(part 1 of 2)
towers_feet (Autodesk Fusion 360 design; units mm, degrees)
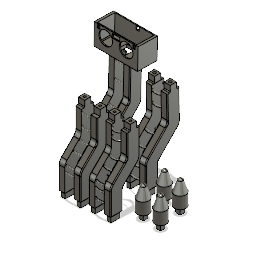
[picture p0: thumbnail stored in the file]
sketch "Sketch1" plane through (0, 0, 0) normal (0, 1, 0) x axis (1, 0, 0)
  line L1 (31.4678, 7.6066) -> (-53.5322, 7.6066)
  line L2 (-53.5322, -77.3934) -> (31.4678, -77.3934)
  line L3 (-53.5322, 7.6066) -> (-53.5322, -77.3934)
  line L4 (-24.0269, 7.6066) -> (-16.0269, 7.6066)
  line L5 (-24.0269, 23.3155) -> (-24.0269, 7.6066)
  line L6 (-16.0269, 7.6066) -> (-16.0269, 23.3155)
  line L7 (3.9731, 7.6066) -> (-4.0269, 7.6066)
  line L8 (3.9731, 23.3155) -> (3.9731, 7.6066)
  line L9 (-4.0269, 7.6066) -> (-4.0269, 23.3155)
  line L10 (-69.5322, -10.1974) -> (-53.5322, -10.1974)
  line L11 (-53.5322, -18.1974) -> (-69.5322, -18.1974)
  line L12 (-53.5322, -10.1974) -> (-53.5322, -18.1974)
  line L13 (-69.5322, -30.1974) -> (-53.5322, -30.1974)
  line L14 (-53.5322, -38.1974) -> (-69.5322, -38.1974)
  line L15 (-53.5322, -30.1974) -> (-53.5322, -38.1974)
  line L16 (-24.0269, -93.3934) -> (-24.0269, -77.3934)
  line L17 (-16.0269, -93.3934) -> (-16.0269, -77.3934)
  line L18 (-4.0269, -93.3934) -> (-4.0269, -77.3934)
  line L19 (3.9731, -93.3934) -> (3.9731, -77.3934)
  line L20 (31.4678, -77.3934) -> (31.4678, 7.6066)
  line L21 (47.4678, -18.1974) -> (31.4678, -18.1974)
  line L22 (47.4678, -10.1974) -> (31.4678, -10.1974)
  line L23 (47.4678, -30.1974) -> (31.4678, -30.1974)
  line L24 (47.4678, -38.1974) -> (31.4678, -38.1974)
  line L25 (-59.6337, -72.3934) -> (-62.6337, -72.3934)
  line L26 (37.4678, -72.3934) -> (40.4678, -72.3934)
  line L27 (-59.6337, 2.6066) -> (-62.6337, 2.6066)
  line L28 (37.4678, 2.6066) -> (40.4678, 2.6066)
  line L29 (-59.6337, -72.3934) -> (-59.6337, 2.6066)
  line L30 (37.4678, 2.6066) -> (37.4678, -72.3934)
  line L31 (-62.6337, -72.3934) -> (-62.6337, 2.6066)
  line L32 (40.4678, -72.3934) -> (40.4678, 2.6066)
  line L33 (-69.5322, -18.1974) -> (-69.5322, -10.1974)
  line L34 (-69.5322, -38.1974) -> (-69.5322, -30.1974)
  line L35 (47.4678, -18.1974) -> (47.4678, -10.1974)
  line L36 (47.4678, -38.1974) -> (47.4678, -30.1974)
  line L37 (-16.0269, -93.3934) -> (-24.0269, -93.3934)
  line L38 (3.9731, -93.3934) -> (-4.0269, -93.3934)
  line L39 (-4.0269, 23.3155) -> (3.9731, 23.3155)
  line L40 (-24.0269, 23.3155) -> (-16.0269, 23.3155)
  line L41 (-5, -80) -> (-15, -80)
  line L42 (-5, -85) -> (-5, -80)
  line L43 (-15, -85) -> (-5, -85)
  line L44 (-15, -80) -> (-15, -85)
  line L45 (-5, 10) -> (-15, 10)
  line L46 (-5, 15) -> (-5, 10)
  line L47 (-15, 15) -> (-5, 15)
  line L48 (-15, 10) -> (-15, 15)
  line L49 (-64, -19) -> (-69, -19)
  line L50 (-64, -29) -> (-64, -19)
  line L51 (-69, -29) -> (-64, -29)
  line L52 (-69, -19) -> (-69, -29)
  line L53 (46.4751, -19) -> (41.4751, -19)
  line L54 (46.4751, -29) -> (46.4751, -19)
  line L55 (41.4751, -29) -> (46.4751, -29)
  line L56 (41.4751, -19) -> (41.4751, -29)
  line L57 (63.9678, 9.8155) -> (63.9678, 30.1039)
  line L58 (-86.0322, -99.8934) -> (-86.0322, -79.8934)
  line L59 (63.9678, -79.8934) -> (63.9678, -99.8934)
  line L60 (53.9678, -109.8934) -> (33.9678, -109.8934)
  line L61 (-76.0322, -109.8934) -> (-56.0322, -109.8934)
  line L62 (-86.0322, 10.1066) -> (-86.0322, 30.1026)
  line L63 (53.9691, 40.1039) -> (33.9678, 40.1066)
  line L64 (-76.0322, 40.1026) -> (-56.0322, 40.1026)
  curve K1 (-62.3587, -78.4407) -> (-62.3587, -78.4407)
  line L65 (-68.03, -97.893) -> (-74.03, -97.893)
  line L66 (-68.03, -91.893) -> (-68.03, -97.893)
  line L67 (-74.03, -91.893) -> (-68.03, -91.893)
  line L68 (-74.03, -97.893) -> (-74.03, -91.893)
  line L69 (51.9678, -97.8934) -> (45.9678, -97.8934)
  line L70 (51.9678, -91.8934) -> (51.9678, -97.8934)
  line L71 (45.9678, -91.8934) -> (51.9678, -91.8934)
  line L72 (45.9678, -97.8934) -> (45.9678, -91.8934)
  line L73 (51.9678, 22.1046) -> (45.9678, 22.1046)
  line L74 (51.9678, 28.1046) -> (51.9678, 22.1046)
  line L75 (45.9678, 28.1046) -> (51.9678, 28.1046)
  line L76 (45.9678, 22.1046) -> (45.9678, 28.1046)
  line L77 (-68, 22) -> (-74, 22)
  line L78 (-68, 28) -> (-68, 22)
  line L79 (-74, 28) -> (-68, 28)
  line L80 (-74, 22) -> (-74, 28)
  line L81 (33.4678, -36.6974) -> (44.9678, -36.6974)
  line L82 (33.4678, -31.6974) -> (33.4678, -36.6974)
  line L83 (44.9678, -31.6974) -> (33.4678, -31.6974)
  line L84 (44.9678, -36.6974) -> (44.9678, -31.6974)
  line L85 (33.4678, -16.6974) -> (44.9678, -16.6974)
  line L86 (33.4678, -11.6974) -> (33.4678, -16.6974)
  line L87 (44.9678, -11.6974) -> (33.4678, -11.6974)
  line L88 (44.9678, -16.6974) -> (44.9678, -11.6974)
  line L89 (-2.5269, 20.8155) -> (2.4731, 20.8155)
  line L90 (-2.5269, 9.3155) -> (-2.5269, 20.8155)
  line L91 (2.4731, 9.3155) -> (-2.5269, 9.3155)
  line L92 (2.4731, 20.8155) -> (2.4731, 9.3155)
  line L93 (-22.5269, 20.8155) -> (-17.5269, 20.8155)
  line L94 (-22.5269, 9.3155) -> (-22.5269, 20.8155)
  line L95 (-17.5269, 9.3155) -> (-22.5269, 9.3155)
  line L96 (-17.5269, 20.8155) -> (-17.5269, 9.3155)
  line L97 (-55.5322, -11.6974) -> (-67.0322, -11.6974)
  line L98 (-55.5322, -16.6974) -> (-55.5322, -11.6974)
  line L99 (-67.0322, -16.6974) -> (-55.5322, -16.6974)
  line L100 (-67.0322, -11.6974) -> (-67.0322, -16.6974)
  line L101 (-55.5322, -31.6974) -> (-67.0322, -31.6974)
  line L102 (-55.5322, -36.6974) -> (-55.5322, -31.6974)
  line L103 (-67.0322, -36.6974) -> (-55.5322, -36.6974)
  line L104 (-67.0322, -31.6974) -> (-67.0322, -36.6974)
  line L105 (-17.5269, -90.8934) -> (-22.5269, -90.8934)
  line L106 (-17.5269, -79.3934) -> (-17.5269, -90.8934)
  line L107 (-22.5269, -79.3934) -> (-17.5269, -79.3934)
  line L108 (-22.5269, -90.8934) -> (-22.5269, -79.3934)
  line L109 (2.4731, -90.8934) -> (-2.5269, -90.8934)
  line L110 (2.4731, -79.3934) -> (2.4731, -90.8934)
  line L111 (-2.5269, -79.3934) -> (2.4731, -79.3934)
  line L112 (-2.5269, -90.8934) -> (-2.5269, -79.3934)
  circle C1 centre (48.9678, 25.1046) radius 7.5
  circle C2 centre (-71.0322, 25.1066) radius 7.5
  circle C3 centre (-71.0322, -94.8934) radius 7.5
  circle C4 centre (48.9678, -94.8934) radius 7.5
  arc A1 centre (-11.0349, 100.0947) radius 74.9921 clockwise from (33.9678, 40.1066) to (-56.0322, 40.1026)
  arc A2 centre (123.5319, -35.039) radius 74.5641 clockwise from (63.9678, -79.8934) to (63.9678, 9.8155)
  arc A3 centre (-11.0322, -169.8934) radius 75 clockwise from (-56.0322, -109.8934) to (33.9678, -109.8934)
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  point P4 (-53.5322, -77.3934)
  point P5 (-53.5322, 7.6066)
  point P28 (-62.6337, -72.3934)
  point P29 (-59.6337, -72.3934)
  point P30 (40.4678, -72.3934)
  point P31 (37.4678, -72.3934)
  point P32 (-62.6337, 2.6066)
  point P33 (-59.6337, 2.6066)
  point P34 (40.4678, 2.6066)
  point P35 (37.4678, 2.6066)
  point P52 (-15, -80)
  point P53 (-5, -80)
  point P55 (-15, -85)
  point P56 (-15, 10)
  point P57 (-5, 10)
  point P59 (-15, 15)
  point P60 (-69, -19)
  point P63 (-69, -29)
  point P64 (41.4751, -19)
  point P65 (46.4751, -19)
  point P67 (41.4751, -29)
  point P96 (-74.03, -97.893)
  point P99 (-74.03, -91.893)
  point P97 (-68.03, -97.893)
  point P19 (48.9678, -94.8934)
  point P112 (44.9678, -36.6974)
  point P113 (33.4678, -36.6974)
  point P115 (44.9678, -31.6974)
  point P116 (44.9678, -16.6974)
  point P117 (33.4678, -16.6974)
  point P119 (44.9678, -11.6974)
  point P120 (2.4731, 20.8155)
  point P121 (-2.5269, 20.8155)
  point P123 (2.4731, 9.3155)
  point P124 (-17.5269, 20.8155)
  point P125 (-22.5269, 20.8155)
  point P127 (-17.5269, 9.3155)
  point P128 (-67.0322, -11.6974)
  point P129 (-55.5322, -11.6974)
  point P131 (-67.0322, -16.6974)
  point P132 (-67.0322, -31.6974)
  point P133 (-55.5322, -31.6974)
  point P135 (-67.0322, -36.6974)
  point P136 (-22.5269, -90.8934)
  point P139 (-22.5269, -79.3934)
  point P137 (-17.5269, -90.8934)
  point P140 (-2.5269, -90.8934)
  point P141 (2.4731, -90.8934)
  point P143 (-2.5269, -79.3934)
  dimension "d124" diameter C2 = 15
  dimension "d162" distance P4 P5 = 85
  dimension "d167" distance L6 L9 = 12
  dimension "d169" distance L11 L13 = 12
  dimension "d179" distance P28 P29 = 3
  dimension "d181" distance P30 P31 = 3
  dimension "d183" distance P32 P33 = 3
  dimension "d186" distance P34 P35 = 3
  dimension "d188" distance L2 L25 = 5
  dimension "d189" distance L2 L26 = 5
  dimension "d192" distance L1 L28 = 5
  dimension "d193" distance L1 L27 = 5
  dimension "d407" distance P52 P53 = 10
  dimension "d408" distance P52 P55 = 5
  dimension "d409" distance P56 P57 = 10
  dimension "d410" distance P56 P59 = 5
  dimension "d412" distance P60 P63 = 10
  dimension "d413" distance P64 P65 = 5
  dimension "d414" distance P64 P67 = 10
  dimension "d502" radius = 10
  dimension "d588" distance P96 P99 = 6
  dimension "d589" distance P96 P97 = 6
  dimension "d597" distance P19 L72 = 3
  dimension "d655" distance P112 P113 = 11.5
  dimension "d656" distance P112 P115 = 5
  dimension "d657" distance L36 L84 = 2.5
  dimension "d658" distance L23 L83 = 1.5
  dimension "d659" distance P116 P117 = 11.5
  dimension "d660" distance P116 P119 = 5
  dimension "d661" distance L21 L85 = 1.5
  dimension "d662" distance L35 L88 = 2.5
  dimension "d663" distance P120 P121 = 5
  dimension "d664" distance P120 P123 = 11.5
  dimension "d665" distance L8 L92 = 1.5
  dimension "d666" distance L39 L89 = 2.5
  dimension "d671" distance P124 P125 = 5
  dimension "d672" distance P124 P127 = 11.5
  dimension "d673" distance L40 L93 = 2.5
  dimension "d674" distance L5 L94 = 1.5
  dimension "d675" distance L6 L96 = 1.5
  dimension "d676" distance P128 P129 = 11.5
  dimension "d677" distance P128 P131 = 5
  dimension "d678" distance L33 L100 = 2.5
  dimension "d679" distance L11 L99 = 1.5
  dimension "d680" distance P132 P133 = 11.5
  dimension "d681" distance P132 P135 = 5
  dimension "d682" distance L34 L104 = 2.5
  dimension "d683" distance L14 L103 = 1.5
  dimension "d684" distance P136 P139 = 11.5
  dimension "d685" distance P136 P137 = 5
  dimension "d686" distance L37 L105 = 2.5
  dimension "d687" distance L17 L106 = 1.5
  dimension "d688" distance P140 P141 = 5
  dimension "d689" distance P140 P143 = 11.5
  dimension "d690" distance L38 L109 = 2.5
  dimension "d691" distance L19 L110 = 1.5
  dimension "d692" distance L106 L112 = 15
  dimension "d693" distance L99 L101 = 15
  dimension "d694" distance L90 L96 = 15
  dimension "d695" distance L83 L85 = 15
extrude "Extrude9" new body sketch "Sketch1" profile of C1 C2 C3 C4 against normal blind 15
sketch "Sketch3" plane through (0, 0, 0) normal (1, 0, 0) x axis (0, 0, -1)
  line L1 (-77.6845, 0) -> (-89.6845, 0)
  line L2 (-81.7624, 30.5676) -> (-81.7624, 0.5676)
  line L3 (-109.6726, 59.221) -> (-81.7624, 30.5676)
  line L4 (-109.0151, 94.2149) -> (-109.6726, 59.221)
  line L5 (23.3155, 0) -> (7.6066, 0)
  line L6 (10, 30.5) -> (10, 0.5)
  line L7 (37.7935, 59.2667) -> (10, 30.5)
  line L8 (38.6405, 99.2577) -> (37.7935, 59.2667)
  point P4 (-81.7624, 0.5676)
  point P5 (-81.7624, 30.5676)
  point P6 (-109.6726, 59.221)
  point P7 (-109.0151, 94.2149)
  point P10 (10, 0.5)
  point P11 (10, 30.5)
  point P12 (37.7935, 59.2667)
  point P13 (38.6405, 99.2577)
  dimension "d21" distance P4 P5 = 30
  dimension "d23" distance P5 P6 = 40
  dimension "d24" distance P6 P7 = 35
  dimension "d26" distance P10 P11 = 30
  dimension "d28" distance P11 P12 = 40
  dimension "d29" distance P12 P13 = 40
sweep "Sweep2" sketch "Sketch1" TwistAngle 0 TaperAngle 0
sweep "Sweep1" sketch "Sketch1" TwistAngle 0 TaperAngle 0
sketch "Sketch4"
  line L1 (31.4678, 0) -> (43.352, 0)
  line L2 (34, 31) -> (34, 1)
  line L3 (55.2132, 52.2132) -> (34, 31)
  line L4 (55.2132, 82.2132) -> (55.2132, 52.2132)
  line L5 (-56.9466, 31) -> (-56.9466, 1)
  line L6 (-78.1598, 52.2132) -> (-56.9466, 31)
  line L7 (-78.1598, 82.2132) -> (-78.1598, 52.2132)
  point P4 (34, 1)
  point P5 (34, 31)
  point P6 (55.2132, 52.2132)
  point P7 (55.2132, 82.2132)
  point P10 (-78.1598, 52.2132)
  point P11 (-78.1598, 82.2132)
  dimension "d42" distance P4 P5 = 30
  dimension "d44" distance P5 P6 = 30
  dimension "d45" distance P6 P7 = 30
  dimension "d415" distance P10 P11 = 30
sweep "Sweep3" sketch "Sketch1" TwistAngle 0 TaperAngle 0
sweep "Sweep4" sketch "Sketch1" TwistAngle 0 TaperAngle 0
fillet "Fillet1" radius 1
work_plane "WorkPlane1" AlongDistance 15
sketch "Sketch8" plane through (-71.0322, -30, -24.8155) normal (0, -1, 0) x axis (1, 0, 0)
  circle C1 centre (0, 0) radius 2.5
  dimension "d136" diameter C1 = 5
loft "Loft1" sketch "Sketch8"
work_plane "WorkPlane2" AlongDistance 15
sketch "Sketch9" plane through (-71.0322, -30, 95.1845) normal (0, -1, 0) x axis (1, 0, 0)
  circle C1 centre (0, 0) radius 2.5
  dimension "d138" diameter C1 = 5
loft "Loft2" sketch "Sketch9"
work_plane "WorkPlane3" AlongDistance 15
sketch "Sketch10" plane through (48.9678, -30, -24.8155) normal (0, -1, 0) x axis (1, 0, 0)
  circle C1 centre (0, 0) radius 2.5
  dimension "d140" diameter C1 = 5
loft "Loft3" sketch "Sketch10"
work_plane "WorkPlane4" AlongDistance 15
sketch "Sketch11" plane through (48.9678, -30, 95.1845) normal (0, -1, 0) x axis (1, 0, 0)
  circle C1 centre (0, 0) radius 2.5
  dimension "d142" diameter C1 = 5
loft "Loft4" sketch "Sketch11"
fillet "Fillet5" radius 3
sketch "Sketch12" plane through (0, 0, 18.1974) normal (0, 0, 1) x axis (1, 0, 0)
  line L1 (-53.5322, 0) -> (-69.5322, 0)
  line L2 (-90.7454, 82.2132) -> (-74.7454, 82.2132)
  line L3 (-53.5322, 32.4143) -> (-53.5322, 0)
  line L4 (-74.7454, 53.6275) -> (-53.5322, 32.4143)
  line L5 (-74.7454, 82.2132) -> (-74.7454, 53.6275)
  line L6 (-90.7454, 47.0001) -> (-90.7454, 82.2132)
  line L7 (-69.5322, 25.7869) -> (-90.7454, 47.0001)
  line L8 (-69.5322, 0) -> (-69.5322, 25.7869)
sketch "Sketch13" plane through (0, 0, 0) normal (0, 1, 0) x axis (1, 0, 0)
sketch "Sketch18" plane through (0, 0, 18.1974) normal (0, 0, 1) x axis (1, 0, 0)
  line L1 (-90.7454, 47.0001) -> (-90.7454, 82.2132)
  line L2 (68.681, 47.0001) -> (68.681, 92.2132)
  circle C1 centre (-89.7454, 79) radius 1
  circle C2 centre (-75.7454, 79) radius 1
  circle C3 centre (-89.7454, 63.5) radius 1
  circle C4 centre (-75.7454, 63.5) radius 1
  circle C5 centre (-87.8667, 48.3965) radius 1
  circle C6 centre (-73.032, 49.7524) radius 1
  circle C7 centre (-65.5074, 41.1094) radius 1
  circle C8 centre (-56.2089, 29.9048) radius 1
  circle C9 centre (-54.7124, 23.0048) radius 1
  circle C10 centre (-54.765, 11.5923) radius 1
  circle C11 centre (-68.3402, 11.4595) radius 1
  circle C12 centre (-68, 23) radius 1
  circle C13 centre (-70, 29) radius 1
  circle C14 centre (-81, 40) radius 1
  circle C15 centre (-89.7454, 79) radius 1
  circle C16 centre (-75.7454, 79) radius 1
  circle C17 centre (-89.7454, 63.5) radius 1
  circle C18 centre (-75.7454, 63.5) radius 1
  circle C19 centre (-81, 40) radius 1
  circle C20 centre (-87.8667, 48.3965) radius 1
  circle C21 centre (-70, 29) radius 1
  circle C22 centre (-68, 23) radius 1
  circle C23 centre (-54.7124, 23.0048) radius 1
  circle C24 centre (-56.2089, 29.9048) radius 1
  circle C25 centre (-65.5074, 41.1094) radius 1
  circle C26 centre (-68.3402, 11.4595) radius 1
  circle C27 centre (-54.765, 11.5923) radius 1
  circle C28 centre (67.681, 69.5) radius 1
  circle C29 centre (53.681, 79) radius 1
  circle C30 centre (53.681, 69.5) radius 1
  circle C31 centre (53.681, 69.5) radius 1
  circle C32 centre (67.681, 69.5) radius 1
  circle C33 centre (67.681, 79) radius 1
  circle C34 centre (46.2758, 11.4595) radius 1
  circle C35 centre (46.2758, 11.4595) radius 1
  circle C36 centre (32.7006, 11.5923) radius 1
  circle C37 centre (32.7006, 11.5923) radius 1
  circle C38 centre (34.1444, 29.9048) radius 1
  circle C39 centre (43.4429, 41.1094) radius 1
  circle C40 centre (43.4429, 41.1094) radius 1
  circle C41 centre (47.9356, 29) radius 1
  circle C42 centre (58.9356, 40) radius 1
  circle C43 centre (47.9356, 29) radius 1
  circle C44 centre (65.8022, 48.3965) radius 1
  circle C45 centre (45.9356, 23) radius 1
  circle C46 centre (65.8022, 48.3965) radius 1
  circle C47 centre (32.648, 23.0048) radius 1
  circle C48 centre (50.9676, 49.7524) radius 1
  circle C49 centre (32.648, 23.0048) radius 1
  circle C50 centre (34.1444, 29.9048) radius 1
  circle C51 centre (67.681, 79) radius 1
  circle C52 centre (45.9356, 23) radius 1
  circle C53 centre (58.9356, 40) radius 1
  point P4 (-89.7454, 79)
  dimension "d269" diameter C1 = 2
  dimension "d270" distance L1 P4 = 1
  dimension "d275" diameter C7 = 2
  dimension "d276" diameter C8 = 2
  dimension "d277" diameter C9 = 2
  dimension "d278" diameter C10 = 2
  dimension "d279" diameter C14 = 2
  dimension "d280" diameter C13 = 2
  dimension "d281" diameter C12 = 2
  dimension "d282" diameter C11 = 2
  dimension "d305" diameter C15 = 2
  dimension "d306" diameter C25 = 2
  dimension "d307" diameter C24 = 2
  dimension "d308" diameter C23 = 2
  dimension "d309" diameter C27 = 2
  dimension "d310" diameter C19 = 2
  dimension "d311" diameter C21 = 2
  dimension "d312" diameter C22 = 2
  dimension "d313" diameter C26 = 2
sketch "Sketch21" plane through (0, 82.2132, 0) normal (0, 1, 0) x axis (-1, 0, 0)
  line L1 (89.7454, 10.1974) -> (75.7454, 10.1974)
  line L2 (90.7454, 18.1974) -> (90.7454, 11.1974)
  line L3 (74.7454, 18.1974) -> (90.7454, 18.1974)
  line L4 (74.7454, 11.1974) -> (74.7454, 18.1974)
  arc A1 centre (75.7454, 11.1974) radius 1 clockwise from (75.7454, 10.1974) to (74.7454, 11.1974)
  arc A2 centre (89.7454, 11.1974) radius 1 clockwise from (90.7454, 11.1974) to (89.7454, 10.1974)
  arc A3 centre (81.1475, 25.0943) radius 11.819 clockwise from (90.2904, 32.584) to (90.7454, 18.1974)
  arc A4 centre (86.0713, 24.3961) radius 12.9112 clockwise from (74.7454, 18.1974) to (75.5878, 31.9324)
  arc A5 centre (-57.1895, 24.4354) radius 7.6575 clockwise from (-56, 32) to (-52.7483, 18.1974)
  arc A6 centre (-64.8318, 24.7359) radius 7.5808 clockwise from (-68.6681, 18.1974) to (-67, 32)
  arc A7 centre (-54.9641, 24.3467) radius 14.8392 clockwise from (-43.4429, 33.699) to (-43.4429, 14.9945)
sweep "Sweep15" sketch "Sketch18" TwistAngle 0 TaperAngle 0
sweep "Sweep14" sketch "Sketch18" TwistAngle 0 TaperAngle 0
sweep "Sweep13" sketch "Sketch18" TwistAngle 0 TaperAngle 0
sweep "Sweep12" sketch "Sketch18" TwistAngle 0 TaperAngle 0
sweep "Sweep11" sketch "Sketch18" TwistAngle 0 TaperAngle 0
sweep "Sweep10" sketch "Sketch18" TwistAngle 0 TaperAngle 0
sweep "Sweep9" sketch "Sketch18" TwistAngle 0 TaperAngle 0
sweep "Sweep16" sketch "Sketch18" TwistAngle 0 TaperAngle 0
sketch "Sketch22" plane through (-4.0269, 0, 0) normal (-1, 0, 0) x axis (0, 0, 1)
  line L1 (120.6441, 94.4334) -> (121.236, 62.9332)
  line L2 (104.6469, 94.1328) -> (120.6441, 94.4334)
  line L3 (105.2309, 63.0501) -> (104.6469, 94.1328)
  line L4 (85.9034, 41.0803) -> (103.8135, 59.4673)
  line L5 (77.3934, 8) -> (77.3934, 20.1476)
  line L6 (93.3934, 20.9607) -> (93.3934, 8)
  line L7 (115.5662, 48.6023) -> (96.7974, 29.3338)
  line L8 (93.3934, 8) -> (77.3934, 8)
  arc A1 centre (101.2395, 62.5575) radius 20 clockwise from (121.236, 62.9332) to (115.5662, 48.6023)
  arc A2 centre (100.2318, 62.9561) radius 5 clockwise from (105.2309, 63.0501) to (103.8135, 59.4673)
  arc A3 centre (107.3934, 20.1476) radius 30 clockwise from (77.3934, 20.1476) to (85.9034, 41.0803)
  arc A4 centre (105.3934, 20.9607) radius 12 clockwise from (93.3934, 20.9607) to (96.7974, 29.3338)
  circle C1 centre (105.5904, 89.151) radius 1
  circle C2 centre (119.5904, 89.4141) radius 1
  circle C3 centre (106.0037, 75.151) radius 1
  circle C4 centre (78.7934, 23.0298) radius 1
  circle C5 centre (92.3934, 20.942) radius 1
  circle C6 centre (86.6872, 39.7487) radius 1
  circle C7 centre (95.8673, 29.9599) radius 1
  circle C8 centre (96.7767, 50.328) radius 1
  circle C9 centre (92.3934, 9.2738) radius 1
  circle C10 centre (78.3934, 9.2818) radius 1
  circle C11 centre (109.69, 44.3203) radius 1
  circle C12 centre (118.2899, 55.8791) radius 1
  circle C13 centre (119.9812, 76.4843) radius 1
  circle C14 centre (-49.2213, 56.4899) radius 1
  circle C15 centre (-17.853, 39.9535) radius 1
  circle C16 centre (-9.1762, 23.2216) radius 1
  circle C17 centre (-36.9694, 75.8924) radius 1
  circle C18 centre (-50.9373, 96.8082) radius 1
  circle C19 centre (-22.0868, 12.4349) radius 1
  circle C20 centre (-50.4009, 77.3377) radius 1
  circle C21 centre (-8.8349, 11.4043) radius 1
  circle C22 centre (-22.0514, 20.7273) radius 1
  circle C23 centre (-37.285, 97.151) radius 1
  circle C24 centre (-32.5795, 36.8076) radius 1
  circle C25 centre (-28.9723, 52.2127) radius 1
  point P18 (106.0037, 75.151)
  point P30 (119.9812, 76.4843)
  point P24 (78.3934, 9.2818)
  point P21 (92.3934, 9.2738)
  point P20 (92.3934, 20.942)
  point P19 (78.7934, 23.0298)
  dimension "d376" distance L3 P18 = 1
  dimension "d377" distance L1 P30 = 1
  dimension "d379" distance L5 P24 = 1
  dimension "d380" distance L6 P21 = 1
  dimension "d381" distance L6 P20 = 1
  dimension "d382" distance L5 P19 = 1.4
sketch "Sketch23" plane through (0, 92.1339, -1.7312) normal (0, 0.9998, -0.0188) x axis (-1, 0, 0)
  line L1 (-3.9731, 107.3969) -> (-3.9731, 121.3969)
  line L2 (4.0269, 106.3969) -> (-2.9731, 106.3969)
  line L3 (4.0269, 122.3969) -> (4.0269, 106.3969)
  line L4 (-2.9731, 122.3969) -> (4.0269, 122.3969)
  line L5 (16.0269, 106.3969) -> (23.0269, 106.3969)
  line L6 (23.0269, 122.3969) -> (16.0269, 122.3969)
  line L7 (-2.9731, -34.3755) -> (4.0269, -34.3755)
  line L8 (16.0269, -49.9951) -> (23.0269, -49.9951)
  line L9 (4.0269, -50.0844) -> (-2.9731, -50.0844)
  arc A1 centre (-2.9731, 121.3969) radius 1 clockwise from (-3.9731, 121.3969) to (-2.9731, 122.3969)
  arc A2 centre (-2.9731, 107.3969) radius 1 clockwise from (-2.9731, 106.3969) to (-3.9731, 107.3969)
  arc A3 centre (10.0269, 114.4613) radius 12.4613 clockwise from (19.5269, 106.3969) to (0.5269, 106.3969)
  arc A4 centre (10.0269, 112.946) radius 13.4004 clockwise from (0.5269, 122.3969) to (19.5269, 122.3969)
  arc A5 centre (10.0194, -62.55) radius 29.903 clockwise from (0, -34.3755) to (20.0387, -34.3755)
  arc A6 centre (9.908, -24.72) radius 27.0436 clockwise from (19.5269, -49.9951) to (0.5269, -50.0844)
sweep "Sweep19" sketch "Sketch22" TwistAngle 0 TaperAngle 0
sweep "Sweep20" sketch "Sketch22" TwistAngle 0 TaperAngle 0
sweep "Sweep18" sketch "Sketch22" TwistAngle 0 TaperAngle 0
sweep "Sweep17" sketch "Sketch22" TwistAngle 0 TaperAngle 0
sketch "Sketch24" plane through (0, 8, 0) normal (0, 1, 0) x axis (-1, 0, 0)
  line L1 (68.5322, 38.1974) -> (54.5322, 38.1974)
  line L2 (69.5322, 30.1974) -> (69.5322, 37.1974)
  line L3 (69.5322, 11.1974) -> (69.5322, 18.1974)
  line L4 (54.5322, 10.1974) -> (68.5322, 10.1974)
  line L5 (53.5322, 37.1974) -> (53.5322, 55.8709)
  line L6 (76.0322, -40.1026) -> (56.0322, -40.1026)
  line L7 (86.0322, -10.1066) -> (86.0322, -30.1026)
  line L8 (86.0322, 99.8934) -> (86.0322, 79.8934)
  line L9 (56.0322, 109.8934) -> (76.0322, 109.8934)
  line L10 (-53.9678, 109.8934) -> (-33.9678, 109.8934)
  line L11 (-63.9678, 79.8934) -> (-63.9678, 99.8934)
  line L12 (-63.9678, -30.1039) -> (-63.9678, -9.8155)
  line L13 (-33.9678, -40.1066) -> (-53.9691, -40.1039)
  line L14 (-41.4751, 19) -> (-41.4751, 29)
  line L15 (-46.4751, 19) -> (-41.4751, 19)
  line L16 (-46.4751, 29) -> (-46.4751, 19)
  line L17 (-41.4751, 29) -> (-46.4751, 29)
  line L18 (69, 19) -> (69, 29)
  line L19 (64, 19) -> (69, 19)
  line L20 (64, 29) -> (64, 19)
  line L21 (69, 29) -> (64, 29)
  line L22 (5, -15) -> (15, -15)
  line L23 (5, -10) -> (5, -15)
  line L24 (15, -10) -> (5, -10)
  line L25 (15, -15) -> (15, -10)
  line L26 (15, 80) -> (15, 85)
  line L27 (5, 80) -> (15, 80)
  line L28 (5, 85) -> (5, 80)
  line L29 (15, 85) -> (5, 85)
  line L30 (16.0269, 93.3934) -> (16.0269, 77.3934)
  line L31 (23.0269, 93.3934) -> (16.0269, 93.3934)
  line L32 (24.0269, 78.3934) -> (24.0269, 92.3934)
  line L33 (53.5322, 77.3934) -> (23.0269, 77.3934)
  line L34 (53.5322, 30.1974) -> (69.5322, 30.1974)
  line L35 (53.5322, 18.1974) -> (53.5322, 30.1974)
  line L36 (69.5322, 18.1974) -> (53.5322, 18.1974)
  line L37 (23.0269, -7.6066) -> (53.5322, -7.6066)
  line L38 (24.0269, -22.3155) -> (24.0269, -8.6066)
  line L39 (16.0269, -23.3155) -> (23.0269, -23.3155)
  line L40 (16.0269, -7.6066) -> (16.0269, -23.3155)
  line L41 (4.0269, -7.6066) -> (16.0269, -7.6066)
  line L42 (4.0269, -23.3155) -> (4.0269, -7.6066)
  line L43 (-3.9731, -23.3155) -> (4.0269, -23.3155)
  line L44 (-3.9731, -8.6066) -> (-3.9731, -23.3155)
  line L45 (-31.4678, -7.6066) -> (-2.9731, -7.6066)
  line L46 (-31.4678, 11.1974) -> (-31.4678, -7.6066)
  line L47 (-46.4678, 10.1974) -> (-32.4678, 10.1974)
  line L48 (-47.4678, 18.1974) -> (-47.4678, 11.1974)
  line L49 (-31.4678, 18.1974) -> (-47.4678, 18.1974)
  line L50 (-31.4678, 30.1974) -> (-31.4678, 18.1974)
  line L51 (-46.4678, 30.1974) -> (-31.4678, 30.1974)
  line L52 (-47.4678, 37.1974) -> (-47.4678, 31.1974)
  line L53 (-32.4678, 38.1974) -> (-46.4678, 38.1974)
  line L54 (-31.4678, 77.3934) -> (-31.4678, 37.1974)
  line L55 (-2.9731, 77.3934) -> (-31.4678, 77.3934)
  line L56 (-3.9731, 92.3934) -> (-3.9731, 78.3934)
  line L57 (4.0269, 93.3934) -> (-2.9731, 93.3934)
  line L58 (4.0269, 77.3934) -> (4.0269, 93.3934)
  line L59 (16.0269, 77.3934) -> (4.0269, 77.3934)
  line L60 (53.5322, 75.8031) -> (53.5322, 77.3934)
  curve K1 (53.5322, 55.8709) -> (53.5322, 75.8031)
  line L61 (53.5322, -7.6066) -> (53.5322, 11.1974)
  arc A1 centre (68.5322, 37.1974) radius 1 clockwise from (68.5322, 38.1974) to (69.5322, 37.1974)
  arc A2 centre (68.5322, 11.1974) radius 1 clockwise from (69.5322, 11.1974) to (68.5322, 10.1974)
  arc A3 centre (54.5322, 11.1974) radius 1 clockwise from (54.5322, 10.1974) to (53.5322, 11.1974)
  arc A4 centre (11.0349, -100.0947) radius 74.9921 clockwise from (-33.9678, -40.1066) to (56.0322, -40.1026)
  arc A5 centre (146.0322, 34.8934) radius 75 clockwise from (86.0322, -10.1066) to (86.0322, 79.8934)
  arc A6 centre (11.0322, 169.8934) radius 75 clockwise from (56.0322, 109.8934) to (-33.9678, 109.8934)
  arc A7 centre (-123.5319, 35.039) radius 74.5641 clockwise from (-63.9678, 79.8934) to (-63.9678, -9.8155)
  arc A8 centre (23.0269, 92.3934) radius 1 clockwise from (23.0269, 93.3934) to (24.0269, 92.3934)
  arc A9 centre (23.0269, 78.3934) radius 1 clockwise from (24.0269, 78.3934) to (23.0269, 77.3934)
  arc A10 centre (23.0269, -8.6066) radius 1 clockwise from (23.0269, -7.6066) to (24.0269, -8.6066)
  arc A11 centre (23.0269, -22.3155) radius 1 clockwise from (24.0269, -22.3155) to (23.0269, -23.3155)
  arc A12 centre (-2.9731, -8.6066) radius 1 clockwise from (-3.9731, -8.6066) to (-2.9731, -7.6066)
  arc A13 centre (-32.4678, 11.1974) radius 1 clockwise from (-31.4678, 11.1974) to (-32.4678, 10.1974)
  arc A14 centre (-46.4678, 11.1974) radius 1 clockwise from (-46.4678, 10.1974) to (-47.4678, 11.1974)
  arc A15 centre (-46.4678, 31.1974) radius 1 clockwise from (-46.4678, 30.1974) to (-47.4678, 31.1974)
  arc A16 centre (-46.4678, 37.1974) radius 1 clockwise from (-47.4678, 37.1974) to (-46.4678, 38.1974)
  arc A17 centre (-32.4678, 37.1974) radius 1 clockwise from (-32.4678, 38.1974) to (-31.4678, 37.1974)
  arc A18 centre (-2.9731, 78.3934) radius 1 clockwise from (-2.9731, 77.3934) to (-3.9731, 78.3934)
  arc A19 centre (-2.9731, 92.3934) radius 1 clockwise from (-3.9731, 92.3934) to (-2.9731, 93.3934)
  arc A20 centre (76.0322, 99.8934) radius 10 clockwise from (76.0322, 109.8934) to (86.0322, 99.8934)
  arc A21 centre (-53.9678, 99.8934) radius 10 clockwise from (-63.9678, 99.8934) to (-53.9678, 109.8934)
  arc A22 centre (-53.9678, -30.1039) radius 10 clockwise from (-53.9691, -40.1039) to (-63.9678, -30.1039)
  arc A23 centre (76.0322, -30.1026) radius 10 clockwise from (86.0322, -30.1026) to (76.0322, -40.1026)
  arc A24 centre (54.5322, 37.1974) radius 1 clockwise from (53.5322, 37.1974) to (54.5322, 38.1974)
sketch "Sketch25" plane through (0, 82.2132, 0) normal (0, 1, 0) x axis (-1, 0, 0)
  line L1 (74.7454, 30.1974) -> (74.7454, 37.1974)
  line L2 (90.7454, 30.1974) -> (74.7454, 30.1974)
  line L3 (90.7454, 37.1974) -> (90.7454, 30.1974)
  line L4 (75.7454, 38.1974) -> (89.7454, 38.1974)
  line L5 (89.7454, 10.1974) -> (75.7454, 10.1974)
  line L6 (90.7454, 18.1974) -> (90.7454, 11.1974)
  line L7 (-52.681, 37.1974) -> (-52.681, 30.1974)
  line L8 (-52.681, 18.1974) -> (-52.681, 11.1974)
  line L9 (-53.681, 10.1974) -> (-67.681, 10.1974)
  line L10 (-67.681, 38.1974) -> (-53.681, 38.1974)
  line L11 (-64.681, 30.1974) -> (-56.681, 30.1974)
  line L12 (-64.681, 38.1974) -> (-64.681, 30.1974)
  line L13 (-56.681, 38.1974) -> (-64.681, 38.1974)
  line L14 (-56.681, 30.1974) -> (-56.681, 38.1974)
  line L15 (-52.681, 30.1974) -> (-67.681, 30.1974)
  line L16 (-68.681, 31.1974) -> (-68.681, 37.1974)
  line L17 (-56.8022, 18.1974) -> (-64.8022, 18.1974)
  line L18 (-56.8022, 10.1974) -> (-56.8022, 18.1974)
  line L19 (-64.8022, 10.1974) -> (-56.8022, 10.1974)
  line L20 (-64.8022, 18.1974) -> (-64.8022, 10.1974)
  line L21 (86.7454, 10.1974) -> (78.7454, 10.1974)
  line L22 (86.7454, 18.1974) -> (86.7454, 10.1974)
  line L23 (78.7454, 18.1974) -> (86.7454, 18.1974)
  line L24 (78.7454, 10.1974) -> (78.7454, 18.1974)
  line L25 (74.7454, 11.1974) -> (74.7454, 18.1974)
  line L26 (86.9672, 30.1974) -> (78.9672, 30.1974)
  line L27 (86.9672, 38.1974) -> (86.9672, 30.1974)
  line L28 (78.9672, 38.1974) -> (86.9672, 38.1974)
  line L29 (78.9672, 30.1974) -> (78.9672, 38.1974)
  line L30 (84.8876, 30.1974) -> (73.0469, 30.1974)
  arc A1 centre (75.7454, 37.1974) radius 1 clockwise from (74.7454, 37.1974) to (75.7454, 38.1974)
  arc A2 centre (89.7454, 37.1974) radius 1 clockwise from (89.7454, 38.1974) to (90.7454, 37.1974)
  point P22 (-56.681, 30.1974)
  point P23 (-64.681, 30.1974)
  point P29 (-64.8022, 18.1974)
  point P30 (-56.8022, 18.1974)
  point P33 (78.7454, 10.1974)
  point P34 (86.7454, 10.1974)
  point P39 (78.9672, 30.1974)
  point P40 (86.9672, 30.1974)
  dimension "d432" distance P22 P23 = 8
  dimension "d433" distance L12 L16 = 4
  dimension "d434" distance P29 P30 = 8
  dimension "d435" distance P33 P34 = 8
  dimension "d436" distance L24 L25 = 4
  dimension "d437" distance P39 P40 = 8
extrude "Extrude20" add sketch "Sketch25" profile of L2 L4 L5 L9 L10 L11 L12 L13 L14 L15 L17 L18 L19 L20 L21 L22 L23 L24 L26 L27 L28 L29 L30 distance 8
sketch "Sketch26" plane through (0, 90.2132, 0) normal (0, 1, 0) x axis (-1, 0, 0)
  line L1 (78.7454, 10.1974) -> (78.7454, 18.1974)
  line L2 (86.7454, 10.1974) -> (78.7454, 10.1974)
  line L3 (86.7454, 18.1974) -> (86.7454, 10.1974)
  line L4 (78.7454, 18.1974) -> (86.7454, 18.1974)
  line L5 (86.9672, 30.1974) -> (78.9672, 30.1974)
  line L6 (78.9672, 30.1974) -> (78.9672, 38.1974)
  line L7 (-56.8022, 10.1974) -> (-64.8022, 10.1974)
  line L8 (-64.8022, 10.1974) -> (-64.8022, 18.1974)
  line L9 (-56.681, 30.1974) -> (-64.681, 30.1974)
  line L10 (-64.681, 30.1974) -> (-64.681, 38.1974)
  circle C1 centre (82.7454, 14.1974) radius 1.75
  circle C2 centre (82.9672, 34.1974) radius 1.75
  circle C3 centre (-60.8022, 14.1974) radius 1.75
  circle C4 centre (-60.681, 34.1974) radius 1.75
  point P6 (82.7454, 14.1974)
  point P7 (82.9672, 34.1974)
  point P11 (-60.8022, 14.1974)
  point P12 (-60.681, 34.1974)
  dimension "d440" diameter C2 = 3.5
  dimension "d441" distance L4 P6 = 4
  dimension "d442" distance L3 P6 = 4
  dimension "d443" distance P7 L5 = 4
  dimension "d444" distance P7 L6 = 4
  dimension "d445" diameter C3 = 3.5
  dimension "d446" diameter C4 = 3.5
  dimension "d447" distance P11 L7 = 4
  dimension "d448" distance P11 L8 = 4
  dimension "d449" distance P12 L9 = 4
  dimension "d450" distance P12 L10 = 4
extrude "Extrude21" cut sketch "Sketch26" profile of C1 C2 C3 C4 against normal blind 16
thread "Thread1"
sketch "Sketch28" plane through (0, 92.1339, -1.7312) normal (0, 0.9998, -0.0188) x axis (-1, 0, 0)
  line L1 (16.0269, 122.3969) -> (23.0269, 122.3969)
  line L2 (16.0269, 106.3969) -> (16.0269, 122.3969)
  line L3 (23.0269, 106.3969) -> (16.0269, 106.3969)
  line L4 (24.0269, 121.3969) -> (24.0269, 107.3969)
  line L5 (16.0269, 110.3969) -> (24.0269, 110.3969)
  line L6 (16.0269, 118.3969) -> (16.0269, 110.3969)
  line L7 (24.0269, 118.3969) -> (16.0269, 118.3969)
  line L8 (24.0269, 110.3969) -> (24.0269, 118.3969)
  line L9 (4, 118.3969) -> (-4, 118.3969)
  line L10 (4, 110.3969) -> (4, 118.3969)
  line L11 (-4, 110.3969) -> (4, 110.3969)
  line L12 (-4, 118.3969) -> (-4, 110.3969)
  line L13 (4.0269, 106.3969) -> (-2.9731, 106.3969)
  arc A1 centre (23.0269, 121.3969) radius 1 clockwise from (23.0269, 122.3969) to (24.0269, 121.3969)
  arc A2 centre (23.0269, 107.3969) radius 1 clockwise from (24.0269, 107.3969) to (23.0269, 106.3969)
  point P10 (24.0269, 110.3969)
  point P11 (16.0269, 110.3969)
  point P13 (24.0269, 118.3969)
  point P14 (19.5269, 106.3969)
  point P15 (-4, 118.3969)
  point P18 (-4, 110.3969)
  dimension "d453" distance P10 P11 = 8
  dimension "d454" distance P10 P13 = 8
  dimension "d455" distance L5 P14 = 4
  dimension "d456" distance P15 P18 = 8
  dimension "d457" distance L11 L13 = 4
extrude "Extrude22" add sketch "Sketch28" profile of L2 L4 L5 L6 L7 L8 L9 L10 L11 L12 along normal blind 8
sketch "Sketch29" plane through (0, 100.1325, -1.8815) normal (0, 0.9998, -0.0188) x axis (-1, 0, 0)
  line L1 (16.0269, 118.3969) -> (24.0269, 118.3969)
  line L2 (16.0269, 110.3969) -> (16.0269, 118.3969)
  line L3 (24.0269, 110.3969) -> (16.0269, 110.3969)
  line L4 (24.0269, 118.3969) -> (24.0269, 110.3969)
  line L5 (-4, 118.3969) -> (4, 118.3969)
  line L6 (-3.9731, 107.3969) -> (-3.9731, 121.3969)
  circle C1 centre (20.0269, 114.3969) radius 1.75
  circle C2 centre (0.0269, 114.3969) radius 1.75
  point P6 (20.0269, 114.3969)
  point P7 (0.0269, 114.3969)
  dimension "d460" diameter C1 = 3.5
  dimension "d461" diameter C2 = 3.5
  dimension "d462" distance L1 P6 = 4
  dimension "d463" distance L4 P6 = 4
  dimension "d464" distance P7 L5 = 4
  dimension "d465" distance P7 L6 = 4
extrude "Extrude23" cut sketch "Sketch29" profile of C1 C2 against normal blind 16
sketch "Sketch30" plane through (0, 100.0311, -2.1185) normal (0, 0.9998, -0.0212) x axis (-1, 0, 0)
  line L1 (16.0269, -34.1368) -> (23.0269, -34.1368)
  line L2 (16.0269, -49.8457) -> (16.0269, -34.1368)
  line L3 (23.0269, -49.8457) -> (16.0269, -49.8457)
  line L4 (24.0269, -35.1368) -> (24.0269, -48.8457)
  line L5 (24.0269, -38.1368) -> (16.0269, -38.1368)
  line L6 (24.0269, -46.1368) -> (24.0269, -38.1368)
  line L7 (16.0269, -46.1368) -> (24.0269, -46.1368)
  line L8 (16.0269, -38.1368) -> (16.0269, -46.1368)
  line L9 (4.0269, -38.1368) -> (-3.9731, -38.1368)
  line L10 (4.0269, -46.1368) -> (4.0269, -38.1368)
  line L11 (-3.9731, -46.1368) -> (4.0269, -46.1368)
  line L12 (-3.9731, -38.1368) -> (-3.9731, -46.1368)
  line L13 (-3.9731, -48.8457) -> (-3.9731, -35.1368)
  line L14 (-2.9731, -34.1368) -> (4.0269, -34.1368)
  arc A1 centre (23.0269, -35.1368) radius 1 clockwise from (23.0269, -34.1368) to (24.0269, -35.1368)
  arc A2 centre (23.0269, -48.8457) radius 1 clockwise from (24.0269, -48.8457) to (23.0269, -49.8457)
  point P10 (16.0269, -38.1368)
  point P11 (24.0269, -38.1368)
  point P13 (16.0269, -46.1368)
  point P14 (-3.9731, -38.1368)
  point P17 (-3.9731, -46.1368)
  dimension "d468" distance P10 P11 = 8
  dimension "d469" distance P10 P13 = 8
  dimension "d470" distance L1 L5 = 4
  dimension "d471" distance L3 L7 = 3.7089
  dimension "d472" distance P14 P17 = 8
  dimension "d473" distance L9 L14 = 4
extrude "Extrude24" add sketch "Sketch30" profile of L2 L4 L5 L6 L7 L8 L9 L10 L11 L12 L13 along normal blind 8
sketch "Sketch32" plane through (0, 108.0294, -2.2878) normal (0, 0.9998, -0.0212) x axis (-1, 0, 0)
  line L1 (16.0269, -46.1368) -> (16.0269, -38.1368)
  line L2 (38.0269, -29.6368) -> (-17.9731, -29.6368)
  line L3 (38.0269, -54.6368) -> (38.0269, -29.6368)
  line L4 (-17.9731, -54.6368) -> (38.0269, -54.6368)
  line L5 (-17.9731, -29.6368) -> (-17.9731, -54.6368)
  line L6 (4, -49.5956) -> (15.9676, -49.5956)
  line L7 (4, -31) -> (4, -49.5956)
  line L8 (35.0269, -51.6368) -> (35.0269, -31)
  line L9 (-14.9731, -31) -> (-14.9731, -51.6368)
  line L10 (-14.9731, -53.1368) -> (-14.9731, -51.6368)
  line L11 (35.0269, -53.1368) -> (35.0269, -51.6368)
  line L12 (15.9676, -31) -> (15.9676, -49.5956)
  line L13 (35.0269, -53.1368) -> (-14.9731, -53.1368)
  line L14 (35.0269, -31) -> (-14.9731, -31)
  point P4 (-17.9731, -29.6368)
  point P5 (38.0269, -29.6368)
  point P7 (-17.9731, -54.6368)
  dimension "d505" distance P4 P5 = 56
  dimension "d506" distance P4 P7 = 25
  dimension "d514" distance L5 L9 = 3
extrude "Extrude29" new body sketch "Sketch32" profile of L2 L3 L4 L5 L8 L9 L10 L11 L13 along normal blind 23
extrude "Extrude28" add sketch "Sketch32" profile of L2 L3 L4 L5 L6 L7 L8 L9 L10 L11 L12 L13 L14 against normal blind 4
sketch "Sketch33" plane through (0, -0.6275, -29.6301) normal (0, 0.0212, 0.9998) x axis (1, 0, 0)
  line L1 (17.9731, 108.0536) -> (-38.0269, 108.0536)
  line L2 (-5.2741, 129.5536) -> (-5.2741, 124.5536)
  line L3 (-5.2741, 129.5536) -> (-14.777, 129.5536)
  line L4 (-14.777, 129.5536) -> (-14.777, 124.5536)
  line L5 (-5.2741, 124.5536) -> (-14.777, 124.5536)
  line L6 (-30.6225, 129.7149) -> (-33.6225, 129.7149)
  line L7 (11.3775, 126.0536) -> (11.3775, 129.8575)
  line L8 (14.3775, 126.0536) -> (11.3775, 126.0536)
  line L9 (14.3775, 129.8575) -> (14.3775, 126.0536)
  line L10 (-33.6225, 126.0536) -> (-33.6225, 129.7149)
  line L11 (-30.6225, 126.0536) -> (-30.6225, 129.7149)
  line L12 (-33.6225, 126.0536) -> (-30.6225, 126.0536)
  line L13 (17.9731, 131.0536) -> (-38.0269, 131.0536)
  line L14 (11.3775, 129.8575) -> (14.3775, 129.8575)
  circle C1 centre (-23.0269, 120.0536) radius 8.75
  circle C2 centre (2.9731, 120.0536) radius 8.75
  point P4 (-23.0269, 120.0536)
  point P5 (2.9731, 120.0536)
  point P13 (11.3775, 126.0536)
  point P14 (14.3775, 126.0536)
  dimension "d521" diameter C1 = 17.5
  dimension "d522" diameter C2 = 17.5
  dimension "d525" distance P4 P5 = 26
  dimension "d529" distance P13 P14 = 3
  dimension "d538" distance P4 L13 = 11
  dimension "d541" distance L3 L13 = 1.5
extrude "Extrude31" cut sketch "Sketch33" profile of C1 L2 L3 L4 L5 C2 L6 L7 L8 L9 L10 L11 L12 against normal blind 5
sketch "Sketch34" plane through (0, -1.1568, -54.6245) normal (0, -0.0212, -0.9998) x axis (-1, 0, 0)
  line L1 (38.0269, 131.0536) -> (38.0269, 104.0536)
  line L2 (-17.9731, 131.0536) -> (38.0269, 131.0536)
  line L3 (-17.9731, 104.0536) -> (-17.9731, 131.0536)
  line L4 (8, 130) -> (4, 130)
  line L5 (8, 126) -> (8, 130)
  line L6 (4, 126) -> (8, 126)
  line L7 (4, 130) -> (4, 126)
  line L8 (38.0269, 104.0536) -> (-17.9731, 104.0536)
  point P6 (4, 130)
  point P7 (8, 130)
  point P9 (4, 126)
  dimension "d542" distance P6 P7 = 4
  dimension "d543" distance P6 P9 = 4
extrude "Extrude32" cut sketch "Sketch34" profile of L4 L5 L6 L7 against normal blind 3
sketch "Sketch35" plane through (0, 108.0294, -2.2878) normal (0, 0.9998, -0.0212) x axis (-1, 0, 0)
  line L1 (15.9676, -31) -> (35.0269, -31)
  line L2 (15.9676, -49.5956) -> (15.9676, -31)
  line L3 (4, -49.5956) -> (15.9676, -49.5956)
  line L4 (4, -46.1368) -> (4, -49.5956)
  line L5 (4.0269, -46.1368) -> (4, -46.1368)
  line L6 (4.0269, -38.1368) -> (4.0269, -46.1368)
  line L7 (4, -38.1368) -> (4.0269, -38.1368)
  line L8 (4, -31) -> (4, -38.1368)
  line L9 (-14.9731, -31) -> (4, -31)
  line L10 (-14.9731, -53.1368) -> (-14.9731, -31)
  line L11 (35.0269, -53.1368) -> (-14.9731, -53.1368)
  line L12 (35.0269, -31) -> (35.0269, -53.1368)
  line L13 (23.4069, -39.1522) -> (-3.0608, -39.1522)
  line L14 (23.4069, -44.9292) -> (23.4069, -39.1522)
  line L15 (-3.0608, -44.9292) -> (23.4069, -44.9292)
  line L16 (-3.0608, -39.1522) -> (-3.0608, -44.9292)
sketch "Sketch36" plane through (-62.6337, 0, 0) normal (-1, 0, 0) x axis (0, 0, 1)
  line L1 (-2.6066, 0) -> (72.3934, 0)
  line L2 (-2.6066, -20) -> (-2.6066, 0)
  line L3 (72.3934, -20) -> (-2.6066, -20)
  line L4 (72.3934, 0) -> (72.3934, -20)
  line L5 (29, -1) -> (19, -1)
  line L6 (29, -11) -> (29, -1)
  line L7 (19, -11) -> (29, -11)
  line L8 (19, -1) -> (19, -11)
  point P6 (19, -1)
  point P9 (19, -11)
  point P7 (29, -1)
  dimension "d548" distance P6 P9 = 10
  dimension "d549" distance P6 P7 = 10
extrude "Extrude34" cut sketch "Sketch36" profile of L5 L6 L7 L8 against normal blind 130
move "Move1"
move "Move2"
move "Move3"
move "Move4"
move "Move5"
move "Move8"
move "Move9"
move "Move10"
move "Move11"
move "Move13"
move "Move14"
move "Move15"
move "Move16"
sketch "Sketch37" plane through (0, 32.0212, 0) normal (0, 1, 0) x axis (-1, 0, 0)
  line L1 (-55.5734, 131.8934) -> (-49.5734, 131.8934)
  line L2 (-55.5734, 137.8934) -> (-55.5734, 131.8934)
  line L3 (-49.5734, 137.8934) -> (-55.5734, 137.8934)
  line L4 (-49.5734, 131.8934) -> (-49.5734, 137.8934)
  circle C1 centre (-52.5734, 134.8934) radius 7.5
extrude "Extrude35" add sketch "Sketch37" profile of L1 L2 L3 L4 distance 8.5
fillet "Fillet18" radius 1
sketch "Sketch39" plane through (0, 37.611, 0) normal (0, 1, 0) x axis (-1, 0, 0)
  line L1 (-61.5593, -72.1066) -> (-61.5593, -78.1066)
  line L2 (-55.5593, -72.1066) -> (-61.5593, -72.1066)
  line L3 (-55.5593, -78.1066) -> (-55.5593, -72.1066)
  line L4 (-61.5593, -78.1066) -> (-55.5593, -78.1066)
  circle C1 centre (-58.5593, -75.1066) radius 7.5
extrude "Extrude36" add sketch "Sketch39" profile of L1 L2 L3 L4 distance 8.5
fillet "Fillet19" radius 1
sketch "Sketch40" plane through (0, 28.605, 0) normal (0, 1, 0) x axis (-1, 0, 0)
  line L1 (68.0322, -212.7936) -> (74.0322, -212.7936)
  line L2 (68.0322, -206.7936) -> (68.0322, -212.7936)
  line L3 (74.0322, -206.7936) -> (68.0322, -206.7936)
  line L4 (74.0322, -212.7936) -> (74.0322, -206.7936)
  circle C1 centre (71.0322, -209.7936) radius 7.5
extrude "Extrude37" add sketch "Sketch40" profile of L1 L2 L3 L4 distance 8.5
fillet "Fillet20" radius 1
sketch "Sketch41" plane through (0, 33.0927, 0) normal (0, 1, 0) x axis (-1, 0, 0)
  line L1 (118.0182, -27.8155) -> (124.0182, -27.8155)
  line L2 (118.0182, -21.8155) -> (118.0182, -27.8155)
  line L3 (124.0182, -21.8155) -> (118.0182, -21.8155)
  line L4 (124.0182, -27.8155) -> (124.0182, -21.8155)
  circle C1 centre (121.0182, -25.1046) radius 7.5
extrude "Extrude38" add sketch "Sketch41" profile of L1 L2 L3 L4 distance 8.5
fillet "Fillet21" radius 1
sketch "Sketch42" plane through (0, 1.9376, 0) normal (0, -1, 0) x axis (1, 0, 0)
  line L1 (-53.5322, 149.7536) -> (-53.5322, 142.7536)
  line L2 (-69.5322, 149.7536) -> (-53.5322, 149.7536)
  line L3 (-69.5322, 142.7536) -> (-69.5322, 149.7536)
  line L4 (-54.5322, 141.7536) -> (-68.5322, 141.7536)
  line L5 (-55.5322, 168.2536) -> (-67.0322, 168.2536)
  line L6 (-55.5322, 163.2536) -> (-55.5322, 168.2536)
  line L7 (-67.0322, 163.2536) -> (-55.5322, 163.2536)
  line L8 (-67.0322, 168.2536) -> (-67.0322, 163.2536)
  line L9 (-55.5322, 148.2536) -> (-67.0322, 148.2536)
  line L10 (-55.5322, 143.2536) -> (-55.5322, 148.2536)
  line L11 (-67.0322, 143.2536) -> (-55.5322, 143.2536)
  line L12 (-67.0322, 148.2536) -> (-67.0322, 143.2536)
  line L13 (-69.5322, 168.7536) -> (-69.5322, 161.7536)
  line L14 (-69.5322, 161.7536) -> (-53.5322, 161.7536)
  line L15 (-54.5322, 169.7536) -> (-68.5322, 169.7536)
  line L16 (-53.5322, 161.7536) -> (-53.5322, 168.7536)
  arc A1 centre (-54.5322, 142.7536) radius 1 clockwise from (-53.5322, 142.7536) to (-54.5322, 141.7536)
  arc A2 centre (-68.5322, 142.7536) radius 1 clockwise from (-68.5322, 141.7536) to (-69.5322, 142.7536)
  point P10 (-67.0322, 168.2536)
  point P11 (-55.5322, 168.2536)
  dimension "d605" distance L3 L12 = 2.5
  dimension "d606" distance L8 L13 = 2.5
  dimension "d607" distance L7 L14 = 1.5
  dimension "d608" distance L5 L15 = 1.5
  dimension "d609" distance L6 L16 = 2
  dimension "d610" distance L4 L11 = 1.5
  dimension "d611" distance L2 L9 = 1.5
  dimension "d612" distance L1 L10 = 2
  dimension "d613" distance L3 L12 = 2.5
  dimension "d616" distance P10 P11 = 11.5
extrude "Extrude39" add sketch "Sketch42" profile of L5 L6 L7 L8 L9 L10 L11 L12 distance 8
sketch "Sketch43" plane through (0, 0, 0) normal (0, -1, 0) x axis (1, 0, 0)
  line L1 (-4.0269, 263.3934) -> (2.9731, 263.3934)
  line L2 (-4.0269, 247.3934) -> (-4.0269, 263.3934)
  line L3 (2.9731, 247.3934) -> (-4.0269, 247.3934)
  line L4 (3.9731, 262.3934) -> (3.9731, 248.3934)
  line L5 (2.4731, 260.8934) -> (-2.5269, 260.8934)
  line L6 (2.4731, 249.3934) -> (2.4731, 260.8934)
  line L7 (-2.5269, 249.3934) -> (2.4731, 249.3934)
  line L8 (-2.5269, 260.8934) -> (-2.5269, 249.3934)
  line L9 (-17.5269, 249.3934) -> (-17.5269, 260.8934)
  line L10 (-22.5269, 249.3934) -> (-17.5269, 249.3934)
  line L11 (-22.5269, 260.8934) -> (-22.5269, 249.3934)
  line L12 (-22.5269, 260.8934) -> (-17.5269, 260.8934)
  line L13 (-23.0269, 247.3934) -> (-16.0269, 247.3934)
  arc A1 centre (2.9731, 262.3934) radius 1 clockwise from (2.9731, 263.3934) to (3.9731, 262.3934)
  arc A2 centre (2.9731, 248.3934) radius 1 clockwise from (3.9731, 248.3934) to (2.9731, 247.3934)
  point P10 (-2.5269, 260.8934)
  point P11 (2.4731, 260.8934)
  point P13 (-2.5269, 249.3934)
  point P14 (-22.5269, 260.8934)
  point P17 (-22.5269, 249.3934)
  point P15 (-17.5269, 260.8934)
  dimension "d617" distance P10 P11 = 5
  dimension "d618" distance P10 P13 = 11.5
  dimension "d619" distance L1 L5 = 2.5
  dimension "d620" distance L4 L6 = 1.5
  dimension "d621" distance P14 P17 = 11.5
  dimension "d622" distance P14 P15 = 5
  dimension "d667" distance L10 L13 = 2
  dimension "d668" distance L3 L7 = 2
extrude "Extrude40" add sketch "Sketch43" profile of L5 L6 L7 L8 L9 L10 L11 L12 distance 8.5
fillet "Fillet22" radius 1
sketch "Sketch44" plane through (0, 0.3611, 0) normal (0, -1, 0) x axis (1, 0, 0)
  line L1 (5.2009, -118.7719) -> (19.2009, -118.7719)
  line L2 (4.2009, -126.7719) -> (4.2009, -119.7719)
  line L3 (20.2009, -126.7719) -> (4.2009, -126.7719)
  line L4 (20.2009, -119.7719) -> (20.2009, -126.7719)
  line L5 (17.7009, -120.2719) -> (6.2009, -120.2719)
  line L6 (17.7009, -125.2719) -> (17.7009, -120.2719)
  line L7 (6.2009, -125.2719) -> (17.7009, -125.2719)
  line L8 (6.2009, -120.2719) -> (6.2009, -125.2719)
  line L9 (17.7009, -140.2719) -> (6.2009, -140.2719)
  line L10 (17.7009, -145.2719) -> (17.7009, -140.2719)
  line L11 (6.2009, -145.2719) -> (17.7009, -145.2719)
  line L12 (6.2009, -140.2719) -> (6.2009, -145.2719)
  line L13 (4.2009, -138.7719) -> (4.2009, -145.7719)
  line L14 (19.2009, -146.7719) -> (5.2009, -146.7719)
  line L15 (20.2009, -138.7719) -> (20.2009, -145.7719)
  arc A1 centre (19.2009, -119.7719) radius 1 clockwise from (19.2009, -118.7719) to (20.2009, -119.7719)
  arc A2 centre (5.2009, -119.7719) radius 1 clockwise from (4.2009, -119.7719) to (5.2009, -118.7719)
  point P10 (6.2009, -120.2719)
  point P11 (17.7009, -120.2719)
  point P13 (6.2009, -125.2719)
  point P14 (6.2009, -140.2719)
  point P15 (17.7009, -140.2719)
  point P17 (6.2009, -145.2719)
  dimension "d628" distance P10 P11 = 11.5
  dimension "d629" distance P10 P13 = 5
  dimension "d630" distance L2 L8 = 2
  dimension "d631" distance L1 L5 = 1.5
  dimension "d632" distance P14 P15 = 11.5
  dimension "d633" distance P14 P17 = 5
  dimension "d634" distance L12 L13 = 2
  dimension "d635" distance L11 L14 = 1.5
  dimension "d669" distance L4 L6 = 2.5
  dimension "d670" distance L10 L15 = 2.5
  dimension "d696" distance L7 L9 = 15
extrude "Extrude41" add sketch "Sketch44" profile of L5 L6 L7 L8 L9 L10 L11 L12 distance 8
fillet "Fillet23" radius 1
sketch "Sketch45" plane through (0, -0.8604, 0) normal (0, -1, 0) x axis (1, 0, 0)
  line L1 (-24.0269, -227.5819) -> (-24.0269, -213.873)
  line L2 (-16.0269, -228.5819) -> (-23.0269, -228.5819)
  line L3 (-16.0269, -212.873) -> (-16.0269, -228.5819)
  line L4 (-23.0269, -212.873) -> (-16.0269, -212.873)
  line L5 (-17.5269, -214.5819) -> (-22.5269, -214.5819)
  line L6 (-17.5269, -226.0819) -> (-17.5269, -214.5819)
  line L7 (-22.5269, -226.0819) -> (-17.5269, -226.0819)
  line L8 (-22.5269, -214.5819) -> (-22.5269, -226.0819)
  line L9 (2.4731, -214.5819) -> (-2.5269, -214.5819)
  line L10 (2.4731, -226.0819) -> (2.4731, -214.5819)
  line L11 (-2.5269, -226.0819) -> (2.4731, -226.0819)
  line L12 (-2.5269, -214.5819) -> (-2.5269, -226.0819)
  line L13 (-4.0269, -228.5819) -> (3.9731, -228.5819)
  arc A1 centre (-23.0269, -213.873) radius 1 clockwise from (-24.0269, -213.873) to (-23.0269, -212.873)
  arc A2 centre (-23.0269, -227.5819) radius 1 clockwise from (-23.0269, -228.5819) to (-24.0269, -227.5819)
  point P10 (-22.5269, -214.5819)
  point P11 (-17.5269, -214.5819)
  point P13 (-22.5269, -226.0819)
  point P14 (-2.5269, -214.5819)
  point P15 (2.4731, -214.5819)
  point P17 (-2.5269, -226.0819)
  dimension "d639" distance P10 P11 = 5
  dimension "d640" distance P10 P13 = 11.5
  dimension "d642" distance L3 L6 = 1.5
  dimension "d643" distance L2 L7 = 2.5
  dimension "d644" distance L4 L5 = 1.7089
  dimension "d645" distance P14 P15 = 5
  dimension "d646" distance P14 P17 = 11.5
  dimension "d650" distance L11 L13 = 2.5
extrude "Extrude42" add sketch "Sketch45" profile of L5 L6 L7 L8 L9 L10 L11 L12 distance 8.5
fillet "Fillet24" radius 1
fillet "Fillet25" radius 2
fillet "Fillet26" radius 1
fillet "Fillet27" radius 1
fillet "Fillet28" radius 1
fillet "Fillet29" radius 10
fillet "Fillet30" radius 10
fillet "Fillet31" radius 10
fillet "Fillet32" radius 4
align "Align1"
move "Move18"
